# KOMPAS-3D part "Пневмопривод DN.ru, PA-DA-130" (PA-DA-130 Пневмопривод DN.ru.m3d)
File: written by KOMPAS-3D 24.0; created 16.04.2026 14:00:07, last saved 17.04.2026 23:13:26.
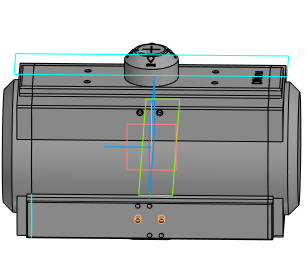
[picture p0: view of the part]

Document properties: Автор: DN.ru; Полное имя файла: C:\Работа\PA-DA-х Пневмопривод DN.ru\130\исходные материалы\PA-DA-130 Пневмопривод DN.ru.m3d

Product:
- Body: Тело 1  | qty 1
    Масса: 43.421893
- Body: Тело 2  | qty 1
    Масса: 43.421893
- Part/product: Пневмопривод DN.ru  | designation PA-DA-130
    Масса: 8.9
    Раздел спецификации: Прочие изделия
    Примечание: D290-00297

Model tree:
1. Эскиз:1
2. Элемент выдавливания:1
3. Эскиз:2  (with: Ребро.Элемент выдавливания:1)
4. Элемент выдавливания:2
5. Эскиз:3  (with: Ребро.Элемент выдавливания:2)
6. Элемент выдавливания:3  (with: Грань.Элемент выдавливания:2)
     Смещение 1 = -2; Расстояние 2 = 133.5; Смещение 2 = -2
7. Эскиз:4  (with: Грань.Элемент выдавливания:3)
8. Элемент выдавливания:4
9. Эскиз:6  (with: Ребро.Элемент выдавливания:2, Ребро.Элемент выдавливания:1)
10. Элемент выдавливания:6
11. Отверстие:2  (with: Грань.Элемент выдавливания:6)
     Глубина выреза = 10; Диаметр отверстия = 5; Угол конуса дна = 120; Расстояние 2 = 4
12. Массив по сетке:2  (with: Отверстие:2)  (3 pattern instances)
     Шаг 1 = 12; Угол раствора = 90; Шаг 2 = 32
13. Массив по сетке:3  (with: Отверстие:2)  (2 pattern instances)
     Шаг 1 = 32; Угол раствора = 90; Шаг 2 = 12
14. Отверстие:3  (with: Грань.Элемент выдавливания:6, Ребро.Элемент выдавливания:6)  (labels: W 1/4'')
     Глубина выреза = 10; Диаметр отверстия = 4.72357; Угол конуса дна = 120; Расстояние 1 = 12; Расстояние 2 = 20
15. W 1/4''  (with: Грань.Отверстие:3, Грань.Элемент выдавливания:6)  (labels: cil5_ex_DIN 477 BSW coarse)
     Длина резьбы = 8; Шаг резьбы = 1.27; Номинальный диаметр резьбы = 6.35
16. Массив по сетке:4  (with: Отверстие:3)  (labels: W 1/4'')  (2 pattern instances)
17. Эскиз:7  (with: Грань.Элемент выдавливания:2)
18. Элемент выдавливания:7
19. Эскиз:8  (with: Грань.Элемент выдавливания:2, Ребро.Элемент выдавливания:2)
20. Элемент выдавливания:8  (with: Грань.Элемент выдавливания:6)
     Расстояние 2 = 4
21. Отверстие:4  (with: Грань.Элемент выдавливания:2)
     Глубина выреза = 7; Диаметр отверстия = 5; Угол конуса дна = 118; Расстояние 1 = 6; Расстояние 2 = 10; Диаметр зенковки = 7; Глубина зенковки = 1; Угол зенковки = 90
22. Массив по сетке:5  (with: Отверстие:4)  (2 pattern instances)
     Шаг 1 = 20; Угол раствора = 90
23. Отверстие:5  (with: Грань.Элемент выдавливания:3)
     Глубина выреза = 10; Диаметр отверстия = 5; Угол конуса дна = 120; Диаметр зенковки = 7; Глубина зенковки = 1; Угол зенковки = 90
24. Массив по сетке:6  (with: Отверстие:5)  (4 pattern instances)
     Угол раствора = 90
25. Фаска:1  (with: Ребро.Элемент выдавливания:4)
     Угол = 45; Длина 1 = 10; Длина 2 = 10
26. Скругление:2  (with: Ребро.Элемент выдавливания:3)
     Радиус = 2
27. Скругление:3  (with: Ребро.Элемент выдавливания:6)
     Радиус = 2
28. Скругление:4  (with: Ребро.Элемент выдавливания:8, Ребро.Элемент выдавливания:2)
     Радиус = 2
29. Скругление:5  (with: Ребро.Элемент выдавливания:6)
     Радиус = 1
30. Смещенная плоскость:1  (with: Грань.Элемент выдавливания:3)
31. Эскиз:9
32. Элемент выдавливания:9  (with: Грань.Фаска:1)
     Расстояние 1 = 35.1642; Смещение 1 = 1
33. Смещенная плоскость:2  (with: Грань.Элемент выдавливания:4)
     Расстояние = 0.5
34. Эскиз:10
35. Элемент выдавливания:10
     Расстояние 1 = 18.4142
36. Эскиз:11  (with: Грань.Элемент выдавливания:4)
37. Элемент выдавливания:11
     Расстояние 1 = 1
38. Эскиз:12  (with: Грань.Элемент выдавливания:11, Ребро.Элемент выдавливания:11)
39. Элемент выдавливания:12  (with: Грань.Элемент выдавливания:4)
     Расстояние 2 = 1
40. Эскиз:13  (with: Грань.Элемент выдавливания:11)
41. Элемент выдавливания:13  (with: Грань.Элемент выдавливания:4)
     Расстояние 2 = 1
42. Скругление:7  (with: Ребро.Элемент выдавливания:11)
     Радиус = 1
43. Скругление:8  (with: Ребро.Элемент выдавливания:2, Ребро.Элемент выдавливания:8)
     Радиус = 2
44. Эскиз:14  (with: Грань.Элемент выдавливания:3)
45. Элемент выдавливания:14  (with: Грань.Фаска:1)
     Расстояние 1 = 46.6414; Смещение 1 = 0.1
46. Эскиз:15  (with: Грань.Элемент выдавливания:3, Ребро.Скругление:2)
47. Элемент выдавливания:15
     Расстояние 2 = 0.1
48. Отверстие:6  (with: Грань.Элемент выдавливания:2, Ребро.Элемент выдавливания:2)
     Глубина выреза = 10; Диаметр отверстия = 8; Угол конуса дна = 118; Расстояние 1 = 10; Расстояние 2 = 10; Диаметр цековки = 15; Глубина цековки = 5
49. Зеркальный массив:1
50. Экземпляр ( 1 )
51. Экземпляр ( 2 )  (with: Отверстие:6)
52. Зеркальный массив:2  (with: Экземпляр ( 1 ), Экземпляр ( 2 ), Отверстие:6)
53. Зеркальный массив:3  (with: Экземпляр ( 1 ), Экземпляр ( 2 ), Зеркальный массив:2, Отверстие:6)
54. Зеркальный массив:4  (with: Экземпляр ( 1 ), Экземпляр ( 2 ), Зеркальный массив:1, Отверстие:6, Зеркальный массив:3, Зеркальный массив:2)
55. Фаска:2  (with: Ребро.Элемент выдавливания:7)
     Угол = 45; Длина 1 = 1; Длина 2 = 1
56. Фаска:3  (with: Ребро.Элемент выдавливания:1)
     Угол = 45; Длина 1 = 10; Длина 2 = 10
57. Смещенная плоскость:3  (with: Грань.Элемент выдавливания:6)
     Расстояние = 5
58. Эскиз:16
59. Элемент выдавливания:16
     Расстояние 2 = 0.1
60. Зеркальный массив:5  (with: Экземпляр ( 1 ), Экземпляр ( 2 ), Элемент выдавливания:16)

Expressions: H/2; -G/2; (E-D-4.5)/2; v2053*2
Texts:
  PA-DA-130
  GOST 26.020 Pr3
